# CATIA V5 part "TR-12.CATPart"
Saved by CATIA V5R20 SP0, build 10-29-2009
Part number: _TR-12
Definition: NONE
Nomenclature: _TR-12
Source: Unknown
Description: PART-_TR-12-DESC
Bounding box of the stored display mesh (mm): x 0 to 12.5, y -6.9 to 6.9, z -6.9 to 6.9
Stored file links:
  C:\Users\Utente\Desktop\IO LAVORO\3D X SITO CF\X SITO\PLASTICA\TR\TR-12.CATPart
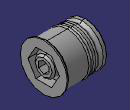
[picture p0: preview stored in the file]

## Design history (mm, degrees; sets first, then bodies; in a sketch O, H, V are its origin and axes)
Body1 "_TR-12" (main body)
  Solid1: solid without history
